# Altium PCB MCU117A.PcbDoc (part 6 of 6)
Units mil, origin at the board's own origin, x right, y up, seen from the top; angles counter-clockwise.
Board outline 2300 x 6749.64 mil, 6 copper layers (Top Signal, GND, Middle Signal, PWR, GND2, Bottom Signal), stack 61.64 mil thick; 424 components, 343 nets, 1563 pads, 921 vias.
Unrouted connection lines stored in the file: 4.
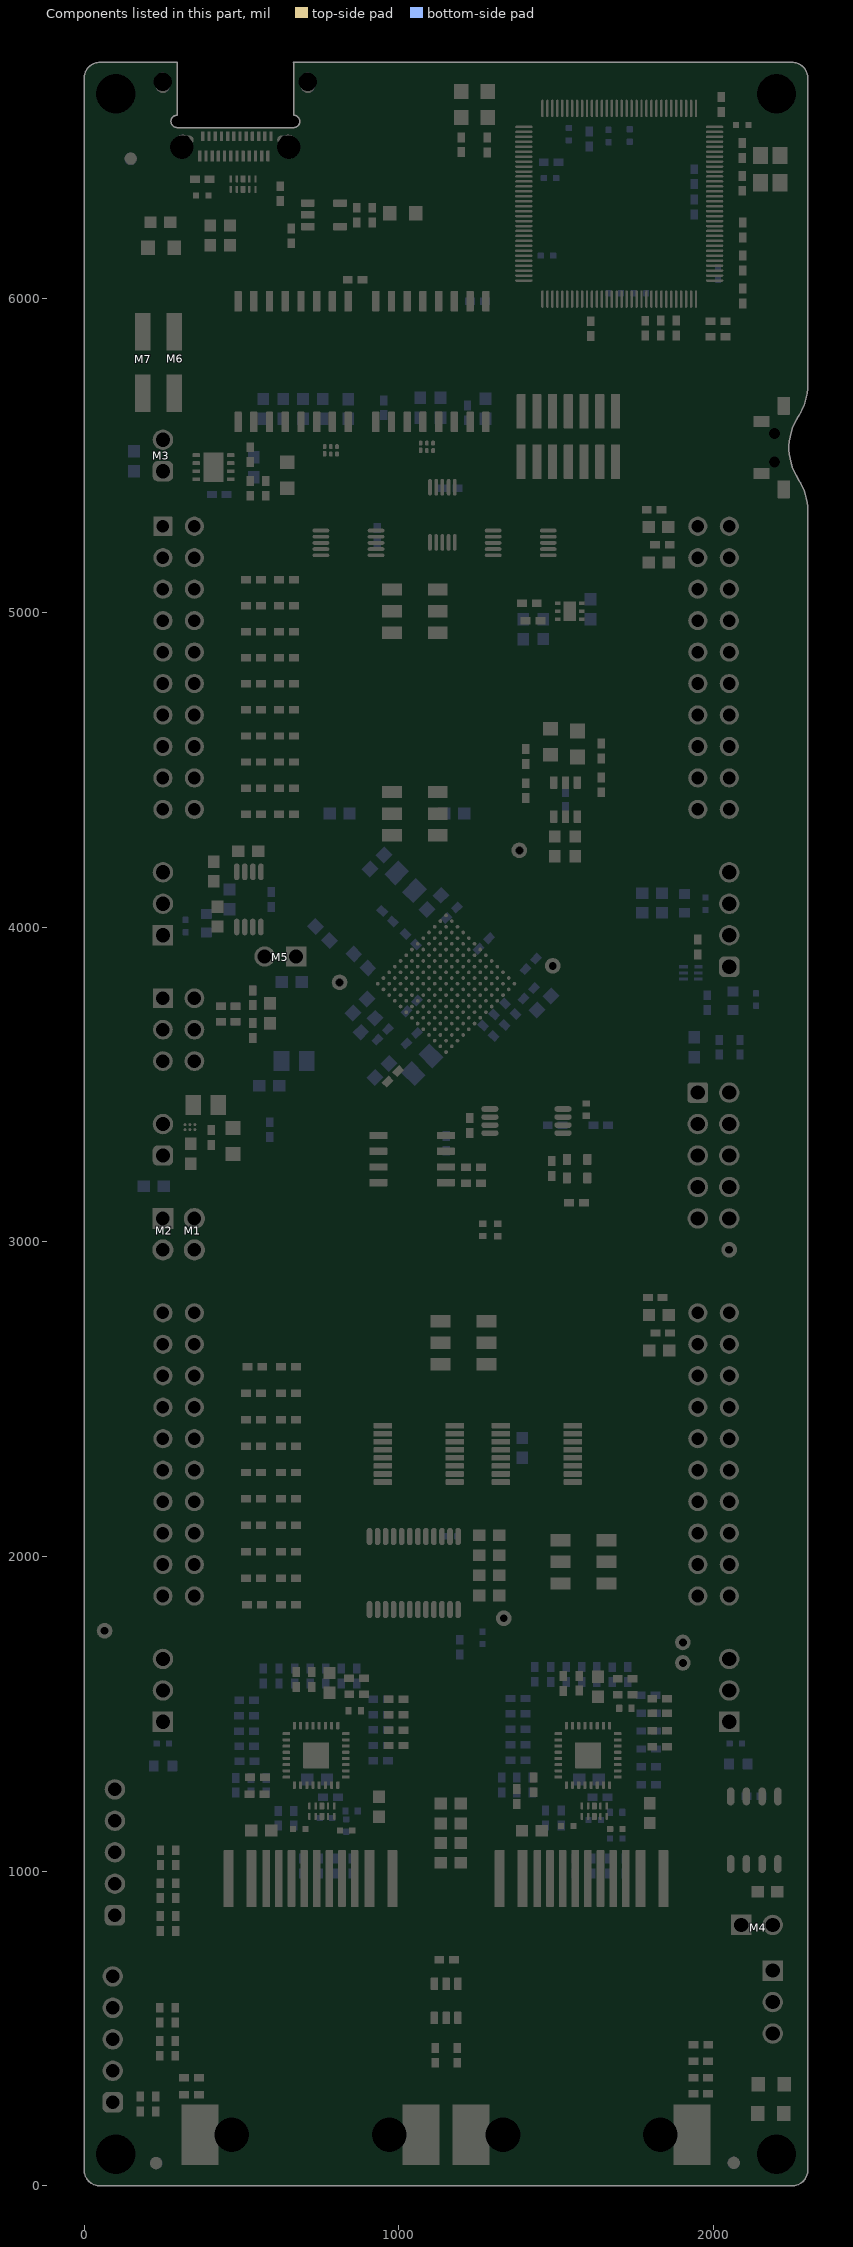
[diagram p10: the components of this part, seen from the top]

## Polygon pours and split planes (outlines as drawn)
VDDIO on PWR "PWR_VDDIO_P129" (solid, pour order 129): 1134.71,3836.63 1134.71,3752.07 1165.72,3752.07 1219.26,3805.61 1219.26,3833.54 1117,3935.81 1076.26,3895.07
VDD on PWR "PWR_VDD_P012" (solid, pour order 12): 1142.58,3884.02 1194.52,3884.02 1194.52,3737.01 1158.6,3737.01 1158.6,3866.88 1142.58,3866.88
VDD on PWR "PWR-VDD 1" (solid, remove dead copper, pour order 115): 1194.52,3847.16 1393,4045.64 1741.08,4045.64 1985.29,3801.43 2026.42,3760.31 2102.75,3760.31 2102.75,3760.55 2128.81,3786.61 2128.81,3935.74 2112.63,3951.92 2033.14,3951.92 1695.66,4289.41 1176.12,4289.41 968.18,4081.46 1151.71,3897.93 1130.2,3876.43 1157.99,3848.64 1157.99,3755.11 1150.89,3748.5 1173.13,3726.25 1194.52,3747.64
VDDA on PWR "PWR-VDDA" (solid, remove dead copper, pour order 63): 733.07,3520.72 868.8,3520.72 991.88,3643.8 967.11,3668.56 1111.46,3806.51 1120.65,3829.72 1120.65,3855.47 1031.91,3944.22 1012.42,3944.22 921.56,4035.08 969.67,4083.19 918.26,4134.6 633.87,4134.6 552.54,4053.28 550.83,3701.8
VDDIO on PWR "PWR_VDDIO_P089" (solid, remove dead copper, pour order 89): 951.95,3655.71 1163.76,3436.41 1739.06,4011.71 1626.38,4124.38 1471.19,4124.38 1196.14,3849.33 1196.14,3739.21 1153.49,3739.43 1153.49,3899.14 969.56,4083.08 921.56,4035.08 1113.49,3843.14 1113.49,3808.97
+3V3_XDS110 on PWR "PWR_+3V3_XDS110_P091" (solid, remove dead copper, pour order 91): 2139.88,6612 2245.98,6505.91 2245.98,6002.85 2245.98,5924.13 2161.85,5840 578.63,5840 519.87,5898.77 519.87,6062.37 821.92,6364.43 1195.43,6364.43 1443,6612
+5V0_USB on PWR "PWR_+5V0_USB_P096" (solid, remove dead copper, pour order 96): 42,5887.96 72.25,5850 487.44,5850 737.88,6277 1078.7,6277 1422.7,6621 2003,6621 2003.07,6621.07 2062.34,6621.07 2079.2,6637.94 2079.2,6708.26 2054.65,6732.81 1354.77,6732.81 1149.95,6527.99 545.98,6527.99 120.99,6527.99 42,6449
+1V2_MCU on PWR "PWR_+1V2_MCU_P097" (solid, remove dead copper, pour order 97): 1322.77,4948.77 1385,5011 1492.73,5011 1541.11,4962.61 1541.11,4652.24 1001.24,4112.37 959.44,4112.37 898.32,4173.5 898.32,4237.5 1322.77,4639.48
+5V0_MCU on PWR "PWR-No Net" (solid, remove dead copper, pour order 116): -0.01,212.95 12,194 358.63,194 378.34,218.93 374,1651.96 443.27,1721.23 1257.11,1721.89 1269,1733.78 1269,1812 1260.68,1828.24 208.08,1828.24 187.43,1848.89 187.61,1849.06 187.61,3130.55 288.45,3130.55 300,3119 300,3057.75 327.75,3030 422.38,3030 472.46,3074.64 472.46,3432.87 429.12,3476.2 213.97,3476.2 173,3501.37 173,3696 207.98,3727.09 446.96,3727.86 469.31,3750.21 469.31,3861.7 469.31,3848.53 469.31,4000.01 429.6,4039.72 217.07,4039.72 180,4076.78 180,5311 203.64,5334.64 284.85,5334.64 299.99,5319.5 299.99,5248.01 414.03,5248.01 433.38,5267.36 433.38,5320.04 211.23,5513.06 211.23,5747.95 16,5747.95 16,3953.78 25.48,3944.3 25.48,3879.84 -0.01,3879.84
VDD on PWR "PWR-VDD" (solid, remove dead copper, pour order 118): 1042.21,1828.27 1312.09,2098.15 1312.09,2280.94 1130.83,2462.2 984.57,2462.2 980.32,2457.95 757.49,2235.12 757.49,1958.27 887.49,1828.27
VDDIO on PWR "PWR-VDDIO" (solid, remove dead copper, pour order 120): 702.9,1732.26 1101.64,1732.26 1405.88,2036.5 1405.88,2346.41 1181.19,2571.1 790.44,2571.1 469.65,2250.31 469.65,1965.51
+3V3_MCU on PWR "PWR_+3V3_MCU_P126" (solid, remove dead copper, pour order 126): 13.52,5745.62 2286,5745.62 2294.66,5736.96 2284.74,5713.97 2284.74,5227.45 2284.74,0 22,0 13.52,8.48
GND on Top Signal "TOP_SIGNAL_GND_P124" (solid, remove dead copper, pour order 124): 21,5747.95 2303.05,5747.95 2305.03,5745.97 2269.64,5663.98 2269.64,0 21,0
GND on Top Signal "TOP_SIGNAL_GND_P125" (solid, remove dead copper, pour order 125): 1086.18,3776.48 1131.86,3838.79 1132.37,3838.79 1139.9,3846.32 1177.09,3846.32 1177.09,3814.14 1215.64,3814.14 1215.64,3780.47 1211.65,3776.48
+3V3_XDS110 on Top Signal "Top Signal-+3V3_XDS110" (solid, remove dead copper, pour order 100): 1368.17,6409.6 1368.17,6317 1368.63,6300.17 1483.03,6300.17 1500.98,6318.12 1500.98,6494.22 1429.03,6494.22 1421.32,6486.51 1421.32,6456.76 1368.17,6456.76
+5V0_USB on Top Signal "TOP_SIGNAL_+5V0_USB_P101" (solid, remove dead copper, pour order 101): 552.11,6322.52 559.99,6330.39 655.39,6330.39 655.39,6351.43 668.1,6364.14 745.81,6364.14 745.81,6287.9 742.63,6284.72 688.59,6284.72 680.98,6277.11 680.98,6252.89 687.87,6246 735.95,6246 745.81,6236.15 745.81,6209.53 731.86,6195.58 562.7,6195.58 547.13,6211.14
+5V0_USB on Top Signal "TOP_SIGNAL_+5V0_USB_P112" (solid, remove dead copper, pour order 112): 18.5,6039.01 211.24,6039.01 211.24,5840 18.5,5840
+3V3_MCU on Top Signal "TOP_SIGNAL_+3V3_MCU_P103" (solid, remove dead copper, pour order 103): 524.74,4210.7 532.01,4217.97 651.99,4217.97 666.67,4203.28 659.51,4196.12 659.51,4115.95 605.92,4062.36 524.74,4062.36
+3V3_MCU on Top Signal "TOP_SIGNAL_+3V3_MCU_P105" (solid, remove dead copper, pour order 105): 1920.44,4079.64 2012.53,4079.64 2039.36,4079.64 2128.81,3990.19 2128.81,3838.09 2107.03,3816.31 1917.92,3816.31
NetJ17_2 on Top Signal "TOP_SIGNAL_NETJ17_2_P107" (solid, remove dead copper, pour order 107): 255.19,3337.2 284.86,3366.87 329.08,3366.87 329.08,3401.67 323.33,3407.41 323.33,3463.54 368.66,3463.54 368.66,3404.02 369.06,3403.61 341.9,3402.76 341.9,3366.87 379.85,3366.87 408.95,3402.89 481.09,3402.89 481.09,3495.31 453.13,3523.26 261.03,3523.26 220,3482.23 220,3351.63 234.51,3337.12
+3V3_MCU on Top Signal "TOP_SIGNAL_+3V3_MCU_P109" (solid, remove dead copper, pour order 109): 447.44,5463.51 504.24,5463.51 505.82,5465.08 510.77,5460.13 510.77,5398.15 593.18,5398.15 623.88,5367.44 623.88,5281.5 603.93,5261.54 461.49,5261.54 445.93,5277.1
NetJ16_2 on Top Signal "TOP_SIGNAL_NETJ16_2_P110" (solid, remove dead copper, pour order 110): 218.79,5609.57 303.11,5609.57 382.94,5529.75 382.94,5389.12 351.78,5350.08 286.97,5406.2 286.97,5499.12 271.38,5514.72 218.79,5514.72
+5V0_MCU on Top Signal "TOP_SIGNAL_+5V0_MCU_P111" (solid, remove dead copper, pour order 111): 21,5747.95 219.7,5747.95 219.7,5569.12 293.39,5495.43 293.39,5400.64 295.61,5400.64 394.46,5301.8 394.46,5233.18 381.27,5220 16,5220
+5V0_MCU on Top Signal "Top Signal-+5V0_MCU" (solid, remove dead copper, pour order 113): 298.77,3036.19 310.94,3024.02 409.09,3024.02 428.73,3043.67 428.73,3198.04 428.73,3320.72 421.07,3328.38 356.89,3328.38 346.1,3339.17 346.1,3367.4 324.39,3389.11 283.05,3389.11 264.46,3370.52 264.46,3277.83 359.93,3277.83 370.25,3267.51 370.25,3140.35 354.67,3124.77 318.35,3124.77 298.77,3105.2
+3V3_ISO_JTAG on Top Signal "TOP_SIGNAL_+3V3_ISO_JTAG_P114" (solid, remove dead copper, pour order 114): 496.71,5724.2 518.13,5745.62 1713.35,5745.62 1755.31,5703.67 1755.31,5548.92 1713.61,5507.22 545.48,5507.22 496.16,5556.54
USB_GND on Top Signal "TOP_SIGNAL_USB_GND_P122" (solid, remove dead copper, pour order 122): 24.5,6732.81 2286,6732.81 2286,5840 24.5,5840
GND on Bottom Signal "BOTTOM_SIGNAL_GND_P106" (solid, remove dead copper, pour order 106): 21,5747.95 2292.22,5747.95 2301.76,5738.4 2292.22,5716.3 2292.22,16 21,16
USB_GND on Bottom Signal "BOTTOM_SIGNAL_USB_GND_P108" (solid, remove dead copper, pour order 108): 25.13,6749 2286,6749 2286,5873.4 2247,5850 50.39,5850 25.13,5869.52
GND on GND "GND_GND_P067" (solid, remove dead copper, pour order 67): -0.36,5747.95 2292.22,5747.95 2292.22,5229.77 2292.22,430.3 -0.36,430.3
ETH1_EARTH on GND "GND_ETH1_EARTH_P064" (solid, remove dead copper, pour order 64): 13.05,588.66 458.87,791.39 1857.19,791.39 2282,580.14 2282,0 13.05,0
USB_GND on GND "GND_USB_GND_P102" (solid, remove dead copper, pour order 102): -1821.32,7027.95 -1769.32,7079.95 392.68,7079.95 431.67,7040.95 431.67,6233.34 392.68,6209.95 -1803.93,6209.95 -1821.32,6223.38
USB_GND on GND "GND_USB_GND_P084" (solid, remove dead copper, pour order 84): -1789.32,7282.95 -1737.32,7334.95 424.68,7334.95 463.67,7295.95 463.67,6488.34 424.68,6464.95 -1771.93,6464.95 -1789.32,6478.38
USB_GND on GND "GND_USB_GND_P083" (solid, remove dead copper, pour order 83): 24.5,6732.81 2286,6732.81 2286,5840 24.5,5840
GND on GND2 "GND2_GND_P086" (solid, remove dead copper, pour order 86): 21,5747.95 2305.88,5747.95 2292.22,5716.29 2292.22,5229.77 2292.22,0 27,0 21,6
USB_GND on GND2 "GND2_USB_GND_P085" (solid, remove dead copper, pour order 85): 21,6720.36 49.64,6749 2286,6749 2286,5840 21,5840

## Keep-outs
Keep-Out Layer:
  lines w7.87: 295.27,6749.64 49.99,6749.64 ccw(c49.99,6699.64) -0.01,6699.64 -0.01,50 ccw(c49.99,50) 49.99,0 2249.99,0 ; 665.35,6749.64 2249.99,6749.64 cw(c2249.99,6699.64) 2299.99,6699.64 2299.99,5724.64 cw(c2118.33,5724.64) 2269.99,5624.64 ccw(c2421.66,5524.64) 2269.99,5424.64 cw(c2118.33,5324.64) 2299.99,5324.64 ; 2249.99,0.65 ccw(c2249.99,50.65) 2299.99,50.65 2293.99,5324.64
  text ".Layer_Name" at 464.64,-1242 h60

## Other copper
Top Signal:
  pour cut-out: 735.98,4527.62 737.35,4526.25 757.13,4526.25 757.13,4094.81 756.27,4093.94 735.98,4093.94
  pour cut-out: 1654.03,4256.72 1670.26,4272.95 1713.89,4272.95 1713.89,3981.57 1662.86,3981.57
  pour cut-out: 1105.42,3801.58 1113.76,3793.24 1113.76,3776.48 1086.18,3776.48
  pour cut-out: 1186.14,3794.95 1215.64,3794.82 1215.64,3780.47 1209.81,3774.64 1186.14,3774.64
  pour cut-out: 1214.06,3813.54 1215.64,3811.96 1215.64,3800.92 1215.14,3800.43 1211.39,3804.18 1211.39,3810.87
  text ".Layer_Name" at 473.64,-1239 h60
Middle Signal:
  text ".Layer_Name" at 476.64,-1238 h60
PWR:
  text ".Layer_Name" at 469.64,-1244 h60
GND:
  text ".Layer_Name" at 469,-1236 h60
GND2:
  text ".Layer_Name" at 470.64,-1242 h60
Bottom Signal:
  pour cut-out: 1395.87,4840 1818.28,4840 1818.28,4812.39 1395.87,4812.39
  pour cut-out: 1711,4303 1716.36,4308.36 1781.49,4308.36 1781.49,4297.54 1832.4,4246.64 1811.66,4225.9 1693.62,4225.9 1693.62,4292.21 1683.18,4302.64
  text ".Layer_Name" at 473.64,-1239 h60

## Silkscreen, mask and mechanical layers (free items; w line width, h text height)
Top Overlay:
  drawing of 12596 lines, arcs and shapes, not listed
  text "*" at 217.75,6362.53 h25
  text "*" at 244.53,6313.28 h25
  text "*" at 2217.9,6203.61 h25
  text "XRSn" at 2098,5694 h72.83
  text "GND" at 378.89,5625.4 h51.18 r90
  text "+5V0" at 113.49,5604.25 h45 r90
  text "ENABLE" at 15.74,5526.42 h51.18
  text "+3V3" at 66.49,5487.63 h51.18
  text "LDO" at 93.22,5447.32 h51.18
  text "IO.8" at 1773.67,5405.39 h51.18
  text "XDS110 Out" at 1404.42,5378.12 h51.18
  text "IO.9" at 1772.68,5367.67 h51.18
  text "*" at 1682.61,5313.88 h25
  text "*" at 1684.89,5201.76 h25
  text "IO.57" at 2114.49,5160.08 h51.18
  text "B0" at 144.72,5155 h51.18
  text "1" at 915.75,5105.59 h51.18
  text "1" at 1168.64,5103.57 h51.18
  text "A14" at 409.16,5094.2 h51.18
  text "IO.84" at 2114.49,5064.67 h51.18
  text "IO.43" at 87.44,5059.62 h51.18
  text "B14" at 409.16,5059.57 h51.18
  text "IO.6" at 1813.29,5059.64 h51.18
  text "*" at 682.3,5050.37 h25
  text "C14" at 409.16,5024.25 h51.18
  text "*" at 685.55,4966.78 h25
  text "SEL1" at 939.15,4961.32 h51.18 r90
  text "SEL2" at 1194.21,4961.32 h51.18 r90
  text "IO.7" at 1813.43,4959.64 h51.18
  text "IO.21" at 2114.49,4959.64 h51.18
  text "A4" at 408.02,4959.25 h51.18
  text "IO.42" at 86.87,4909.64 h51.18
  text "0" at 1166.94,4902.45 h51.18
  text "0" at 910.91,4897.73 h51.18
  text "*" at 684.96,4884.72 h25
  text "IO.10" at 1790.49,4859.64 h51.18
  text "XRSn" at 2114.49,4859.64 h51.18
  text "B4" at 408.02,4859.25 h51.18
  text "SEL1:" at 803.73,4837.28 h51.18
  text "IO42," at 981.04,4837.28 h51.18
  text "IO38," at 1161.42,4837.28 h51.18
  text "*" at 684.67,4802.07 h25
  text "SEL2" at 803.73,4787.28 h51.18
  text "IO43" at 981.04,4787.28 h51.18
  text "IO55" at 1161.42,4787.28 h51.18
  text "C0" at 142.45,4759.64 h51.18
  text "C4" at 408.02,4759.64 h51.18
  text "IO.11" at 1792.2,4759.64 h51.18
  text "IO.16" at 2114.49,4759.62 h51.18
  text ":" at 872.04,4726.78 h51.18
  text "0" at 837.04,4722.78 h51.18
  text "0" at 890.66,4722.78 h51.18
  text "XDS" at 1005.42,4722.78 h51.18
  text "BP" at 1198.71,4722.78 h51.18
  text "*" at 685.55,4718.26 h25
  text ":" at 872.91,4664.28 h51.18
  text "IO.18" at 86.59,4660.77 h51.18
  text "A7" at 408.02,4660.74 h51.18
  text "0" at 837.91,4660.28 h51.18
  text "1" at 897.91,4660.28 h51.18
  text "XDS" at 1005.42,4660.28 h51.18
  text "NC" at 1198.71,4660.28 h51.18
  text "IO.14" at 1789.88,4659.64 h51.18
  text "IO.17" at 2114.49,4659.64 h51.18
  text "*" at 685.26,4635.9 h25
  text ":" at 873.13,4602.28 h51.18
  text "1" at 843.13,4598.28 h51.18
  text "0" at 891.75,4598.28 h51.18
  text "BP" at 1027.42,4598.28 h51.18
  text "BP" at 1198.71,4598.28 h51.18
  text "IO.72" at 86.87,4559.64 h51.18
  text "B7" at 408.02,4559.64 h51.18
  text "IO.15" at 1790.97,4559.62 h51.18
  text "IO.12" at 2114.49,4559.64 h51.18
  text "*" at 684.38,4553.25 h25
  text ":" at 873.48,4540.86 h51.18
  text "1" at 843.48,4536.86 h51.18
  text "1" at 898.48,4536.86 h51.18
  text "BP" at 1027.42,4536.86 h51.18
  text "XDS" at 1182.17,4536.86 h51.18
  text "*" at 684.67,4470.61 h25
  text "IO.105" at 64.12,4459.64 h51.18
  text "C7" at 408.02,4459.64 h51.18
  text "IO.4" at 1813.01,4459.64 h51.18
  text "IO.23" at 2114.49,4459.64 h51.18
  text "1" at 917.13,4456.84 h51.18
  text "1" at 1170.02,4454.82 h51.18
  text "*" at 684.96,4387.67 h25
  text "IO.104" at 63.04,4359.64 h51.18
  text "A0" at 408.02,4359.64 h51.18
  text "IO.5" at 1814.09,4359.64 h51.18
  text "IO.133" at 2114.49,4359.64 h51.18
  text "*" at 685.55,4303.56 h25
  text "GPIO72" at 896.62,4286.89 h51.18 r90
  text "GPIO84" at 1230.83,4286.89 h51.18 r90
  text "0" at 1168.32,4253.7 h51.18
  text "0" at 912.28,4248.99 h51.18
  text "BOOT" at 984.62,4201.64 h51.18
  text "VDD" at 1272.12,4189.64 h51.18
  text "VREFHI" at 646.92,3987.64 h51.18
  text "VDDIO" at 1530.95,3845.45 h51.18
  text "*" at 620.46,3812.78 h25
  text "C8" at 408.82,3765.99 h51.18
  text "B8" at 119.03,3751.66 h51.18
  text "*" at 691.04,3708.33 h25
  text "VDDA" at 750.38,3699.87 h51.18
  text "B9" at 118.57,3648.11 h51.18
  text "*" at 633.37,3628.5 h25
  text "C9" at 408.57,3626.46 h51.18
  text "LAUNCHXL-F28P65X" at 1405.82,3610.57 h50 r0.23
  text "FSI" at 1932.39,3526.97 h51.18
  text "RXCLK" at 1700.22,3454.28 h51.18
  text "TXCLK" at 2109.99,3449.64 h51.18
  text "ENABLE" at 21.44,3350.75 h51.18
  text "+5V0" at 71.82,3312.62 h51.18
  text "BOOST" at 39.51,3272.31 h51.18
  text "TXD0" at 2109.99,3249.64 h51.18
  text "RXD0" at 1754.99,3239.64 h51.18
  text "RXD1" at 1774.99,3144.64 h51.18
  text "TXD1" at 2109.99,3144.64 h51.18
  text "*" at 1630.71,3109.97 h25
  text "+5V0 / TO / J7" at 419.99,2954.64 h51.18
  text "+3V3 / TO / J5" at 36.99,2948.66 h51.18
  text "GND" at 2078.85,2924.98 h51.18
  text "IO.2" at 1774,2903.44 h51.18
  text "IO.3" at 1774.15,2866.89 h51.18
  text "*" at 1681.27,2810.57 h25
  text "BP" at 1035.23,2734.03 h51.18
  text "BP" at 1325.23,2734.03 h51.18
  text "*" at 1680.84,2693.02 h25
  text "Q1" at 1031.33,2664.03 h51.18
  text "Q2" at 1325.23,2664.09 h51.18
  text "A5" at 142.99,2659.64 h51.18
  text "IO.94" at 2109.49,2659.64 h51.18
  text "A15" at 408.02,2594.53 h51.18
  text "J12" at 1010.23,2594.03 h51.18
  text "J13" at 1325.23,2594.03 h51.18
  text "IO.55" at 86.09,2559.64 h51.18
  text "B15" at 408.02,2559.93 h51.18
  text "IO.24" at 2109.49,2559.64 h51.18
  text "IO.0" at 1814.69,2554.64 h51.18
  text "*" at 694.41,2549.34 h25
  text "C15" at 408.02,2525.29 h51.18
  text "QEP Select" at 1083.93,2517.28 h51.18
  text "*" at 694.41,2464.58 h25
  text "IO.79" at 2109.49,2459.64 h51.18
  text "A8" at 409.02,2459.27 h51.18
  text "IO.1" at 1816.39,2449.64 h51.18
  text "IO.38" at 85.43,2409.67 h51.18
  text "*" at 694.6,2381.06 h25
  text "IO.99" at 1791.6,2359.64 h51.18
  text "XRSn" at 2109.49,2359.64 h51.18
  text "B3" at 408.02,2359.25 h51.18
  text "*" at 694.41,2297.73 h25
  text "C1" at 142.99,2259.64 h51.18
  text "C5" at 408.02,2259.69 h51.18
  text "IO.75" at 1792.03,2259.64 h51.18
  text "IO.91" at 2109.49,2259.64 h51.18
  text "*" at 694.6,2213.23 h25
  text "IO.32" at 1791.65,2164.64 h51.18
  text "IO.93" at 86.28,2159.62 h51.18
  text "A10" at 405.02,2159.62 h51.18
  text "IO.92" at 2109.49,2159.64 h51.18
  text "CAN" at 1542.32,2154.01 h51.18
  text "*" at 694.41,2129.04 h25
  text "ROUTE" at 1514.74,2110.02 h51.18
  text "BP" at 1426.36,2073.95 h51.18
  text "IO.82" at 85.71,2059.67 h51.18
  text "B6" at 408.02,2059.69 h51.18
  text "IO.13" at 2109.49,2059.64 h51.18
  text "IO.41" at 1793.26,2054.64 h51.18
  text "*" at 694.41,2044.21 h25
  text "*" at 1429.43,1988.74 h25
  text "IO.35" at 86.09,1959.62 h51.18
  text "C6" at 408.02,1959.67 h51.18
  text "*" at 694.41,1959.81 h25
  text "IO.37" at 1791.37,1959.64 h51.18
  text "IO.103" at 2109.49,1959.64 h51.18
  text "*" at 1430.97,1930.05 h25
  text "*" at 694.41,1877.03 h25
  text "IO.34" at 85,1859.64 h51.18
  text "B1" at 408.02,1859.6 h51.18
  text "IO.25" at 2109.49,1859.64 h51.18
  text "IO.36" at 1791.23,1854.64 h51.18
  text "XCVR" at 1375.55,1845.52 h51.18
  text "*" at 695.35,1793.36 h25
  text "+5V0" at 103.49,1749.07 h51.18
  text "CANTX" at 1742.33,1710.32 h51.18
  text "+3V3" at 1267.76,1686.31 h51.18
  text "CANRX" at 1738.92,1648.9 h51.18
  text "GND" at 10.97,1301.69 h51.18 r270
  text "*" at 1303.82,1199.92 h25
  text "5V" at 10.97,1186.69 h51.18 r270
  text "EQEP2" at 167.44,1124.54 h51.18 r270
  text "*" at 967.25,1101.14 h25
  text "*" at 1634.34,1095.42 h25
  text "2I" at 10.97,1083.07 h51.18 r270
  text "*" at 1792.01,1080.78 h25
  text "*" at 1307.23,1075.11 h25
  text "*" at 797.56,1072.85 h25
  text "2B" at 10.97,986.69 h51.18 r270
  text "2A" at 10.97,886.69 h51.18 r270
  text "P1" at 1051.77,861.56 h100
  text "P0" at 1916,861.56 h100
  text "GND" at 8.25,704.29 h51.18 r270
  text "HI" at 2282,667 h51.18 r90
  text "5V" at 8.25,589.29 h51.18 r270
  text "LO" at 2284.74,561.05 h51.18 r90
  text "CAN" at 2105.52,540.4 h60 r90
  text "EQEP1" at 165.22,530.81 h51.18 r270
  text "1I" at 8.25,480.04 h51.18 r270
  text "GND" at 2284.74,442.15 h51.18 r90
  text "1B" at 8.25,384.29 h51.18 r270
  text "1A" at 8.25,284.29 h51.18 r270
  text ".Layer_Name" at 467.64,-1242 h60
Bottom Overlay:
  drawing of 12861 lines, arcs and shapes, not listed
  text "LAUNCHXL-F28P65X / Development Kit" at 2299.99,6570.51 h100
  text "www.ti.com/launchpad" at 2299.99,5751.92 h100
  text "J3/J1" at 369.58,5346.31 h66.93
  text "J2/J4" at 2068.24,5343.78 h66.93
  text "40" at 1882.99,5259.64 h51.18
  text "39" at 1882.71,5163.74 h51.18
  text "2" at 182.99,5159.64 h51.18
  text "19" at 2161.99,5159.64 h51.18
  text "38" at 1882.99,5064.64 h51.18
  text "3" at 182.99,5059.64 h51.18
  text "23" at 466.99,5059.64 h51.18
  text "18" at 2161.99,5059.64 h51.18
  text "4" at 182.99,4959.64 h51.18
  text "24" at 466.99,4959.64 h51.18
  text "37" at 1882.99,4959.64 h51.18
  text "17" at 2161.99,4959.64 h51.18
  text "5" at 182.99,4859.64 h51.18
  text "25" at 466.99,4859.64 h51.18
  text "36" at 1882.99,4859.64 h51.18
  text "16" at 2161.99,4859.64 h51.18
  text "6" at 182.99,4759.64 h51.18
  text "26" at 466.99,4759.64 h51.18
  text "35" at 1882.99,4759.64 h51.18
  text "15" at 2161.99,4759.64 h51.18
  text "7" at 182.99,4659.64 h51.18
  text "27" at 466.99,4659.64 h51.18
  text "34" at 1882.99,4659.64 h51.18
  text "14" at 2161.99,4659.64 h51.18
  text "8" at 182.99,4559.64 h51.18
  text "28" at 466.99,4559.64 h51.18
  text "33" at 1882.99,4559.64 h51.18
  text "13" at 2161.99,4559.64 h51.18
  text "9" at 182.99,4459.64 h51.18
  text "29" at 466.99,4459.64 h51.18
  text "32" at 1882.99,4459.64 h51.18
  text "12" at 2161.99,4459.64 h51.18
  text "'.PRJ_Number'.PCB_Rev" at 1411.86,4458.85 h108.27
  text "10" at 182.99,4359.64 h51.18
  text "31" at 1882.99,4359.64 h51.18
  text "11" at 2151.99,4359.64 h51.18
  text "30" at 466.17,4358.97 h51.18
  text "*" at 1649.06,4096.47 h25
  text "*" at 478.48,3833.45 h25
  text "*" at 631.85,3626.61 h25
  text "*" at 478.52,3589.81 h25
  text "*" at 1348.02,3358.41 h25
  text "J6/J8" at 2072.3,2848.54 h66.93
  text "J7/J5" at 370.45,2847.62 h66.93
  text "80" at 1882.99,2764.64 h51.18
  text "42" at 182.99,2659.64 h51.18
  text "79" at 1882.99,2659.64 h51.18
  text "59" at 2166.99,2659.2 h51.18
  text "43" at 182.99,2559.64 h51.18
  text "63" at 466.99,2559.64 h51.18
  text "78" at 1882.99,2559.64 h51.18
  text "58" at 2166.99,2559.2 h51.18
  text "44" at 182.99,2459.64 h51.18
  text "64" at 466.99,2459.64 h51.18
  text "77" at 1882.99,2459.64 h51.18
  text "57" at 2166.99,2459.2 h51.18
  text "45" at 182.99,2359.64 h51.18
  text "65" at 466.99,2359.64 h51.18
  text "76" at 1882.99,2359.64 h51.18
  text "56" at 2166.99,2359.2 h51.18
  text "46" at 182.99,2259.64 h51.18
  text "66" at 466.99,2259.64 h51.18
  text "75" at 1882.99,2259.64 h51.18
  text "55" at 2166.99,2259.2 h51.18
  text "47" at 182.99,2159.64 h51.18
  text "67" at 466.99,2159.64 h51.18
  text "74" at 1882.99,2159.64 h51.18
  text "54" at 2166.99,2159.2 h51.18
  text "48" at 182.99,2059.64 h51.18
  text "68" at 466.99,2059.64 h51.18
  text "73" at 1882.99,2059.64 h51.18
  text "53" at 2166.99,2059.2 h51.18
  text "49" at 182.99,1959.64 h51.18
  text "69" at 466.99,1959.64 h51.18
  text "72" at 1882.99,1959.64 h51.18
  text "52" at 2166.99,1959.2 h51.18
  text "50" at 182.99,1859.64 h51.18
  text "70" at 466.99,1859.64 h51.18
  text "71" at 1882.99,1859.64 h51.18
  text "51" at 2156.99,1859.64 h51.18
  text "GND" at 223.26,1244.84 h51.18
  text "5V" at 52.99,1144.96 h51.18
  text "*" at 974.78,1127.22 h25
  text "*" at 696.41,1108.67 h25
  text "*" at 1554.5,1100.51 h25
  text "*" at 1804.16,1091.43 h25
  text "2I" at 47.36,1047.44 h51.18
  text "2B" at 52.4,949.92 h51.18
  text "2A" at 53.21,852.4 h51.18
  text "GND" at 215.1,653.12 h51.18
  text "5V" at 52.99,550.6 h51.18
  text "1I" at 46.16,452.35 h51.18
  text "1B" at 51.19,354.09 h51.18
  text "1A" at 52,255.84 h51.18
  text ".Layer_Name" at 464.64,-1239 h60
Top Paste:
  text ".Layer_Name" at 470.64,-1236 h60
Bottom Paste:
  text ".Layer_Name" at 461.64,-1239 h60
Top Solder:
  text ".Layer_Name" at 458.64,-1248 h60
Bottom Solder:
  text ".Layer_Name" at 455.64,-1233 h60
Drill Guide:
  text ".Layer_Name" at 479.64,-1237.5 h60
M1 Board Outline:
  lines w10: 294.91,6749 49.64,6749 ccw(c49.64,6699) -0.36,6699 -0.36,50 ccw(c49.64,50) 49.64,0 2249.64,0 ccw(c2249.64,50) 2299.64,50 2299.64,5324 ccw(c2117.97,5324) 2269.64,5424 cw(c2421.3,5524) 2269.64,5624 ccw(c2117.97,5724) 2299.64,5724 2299.64,6699 ccw(c2249.64,6699) 2249.64,6749 664.99,6749
  text ".Layer_Name" at 470.77,-1238.3 h60
M2 Board Dimensions:
  text ".Layer_Name" at 476.76,-1239.91 h60
M3 3D STEP Top:
  text ".Layer_Name" at 469.64,-1234.5 h60
M4 3D STEP Bottom:
  text ".Layer_Name" at 470.83,-1236.53 h60
M5 Assembly Top:
  lines w10: -395.86,-1306.67 6204.14,-1306.67 ; -395.86,-1103.34 6206.14,-1103.34 ; -395.86,-900 -395.86,-1510 3609.14,-1510 6206.14,-1510 6206.14,-900 -395.36,-900 -395.36,-1510 1180.14,-1510 ; 2069.14,-1510 2069.14,-900 ; 3336.14,-1103.34 3336.14,-900 ; 4176.14,-1103.34 4176.14,-900 ; 4798.14,-1516.5 4798.14,-1313.67
  text "COMPONENTS MARKED 'DNP' SHOULD NOT BE POPULATED." at 1049.64,-695 h60
  text "ASSEMBLY VARIANT:" at 1049.14,-810.5 h60
  text ".VariantName" at 2085.14,-810.5 h60
  text "PCB VIEWED FROM TOP SIDE" at -332.36,-1032.17 h60
  text "BOARD #:" at 2144.14,-1032.17 h60
  text ".PRJ_Number" at 2689.64,-1032.17 h60
  text "REV:" at 3534.14,-1032.17 h60
  text ".PCB_Rev" at 3825.64,-1032.17 h60
  text "SVN REV:" at 4372.14,-1032.17 h60
  text ".VersionControl_RevNumber" at 4878.14,-1032.17 h60
  text ".Layer_Name" at 476.14,-1236.5 h60
  text "TID #:" at 2144.14,-1235.5 h60
  text ".TID" at 2689.64,-1235.5 h60
  text "PLOT NAME =" at -332.36,-1440.84 h60
  text ".plot_File_Name" at 473.14,-1440.84 h60
  text "GENERATED    :" at 2146.14,-1440.84 h60
  text ".Print_Date" at 3015.64,-1440.84 h60
  text ".Print_Time" at 3744.64,-1440.84 h60
  text "TEXAS INSTRUMENTS" at 5009.14,-1440.84 h60
M6 Assembly Bottom:
  lines w10: -395.36,-1104.34 6206.64,-1104.34 ; -393.36,-1307.67 6206.64,-1307.67 ; 1012.64,-1517.5 1012.64,-1314.67 ; 1634.64,-1104.34 1634.64,-901 ; 2474.64,-1104.34 2474.64,-901 ; 3741.64,-1511 3741.64,-901 ; 4630.64,-1511 6206.14,-1511 6206.14,-901 -395.36,-901 -395.36,-1511 2201.64,-1511 6206.64,-1511 6206.64,-901
  text "COMPONENTS MARKED 'DNP' SHOULD NOT BE POPULATED." at 5999.14,-695 h60
  text ".VariantName" at 4955.14,-811 h60
  text "ASSEMBLY VARIANT:" at 5994.14,-811 h60
  text ".VersionControl_RevNumber" at 932.64,-1033.17 h60
  text "SVN REV:" at 1438.64,-1033.17 h60
  text ".PCB_Rev" at 1985.14,-1033.17 h60
  text "REV:" at 2276.64,-1033.17 h60
  text ".PRJ_Number" at 3121.14,-1033.17 h60
  text "BOARD #:" at 3666.64,-1033.17 h60
  text "PCB VIEWED FROM BOTTOM SIDE" at 6143.14,-1033.17 h60
  text ".Layer_Name" at 477.14,-1237 h60
  text ".TID" at 3121.14,-1236.5 h60
  text "TID #:" at 3666.64,-1236.5 h60
  text "TEXAS INSTRUMENTS" at 801.64,-1441.84 h60
  text ".Print_Time" at 2066.14,-1441.84 h60
  text ".Print_Date" at 2795.14,-1441.84 h60
  text "GENERATED    :" at 3664.64,-1441.84 h60
  text ".plot_File_Name" at 5337.64,-1441.84 h60
  text "PLOT NAME =" at 6143.14,-1441.84 h60
M7 LPKF Text Top:
  text ".Layer_Name" at 477.13,-1232.8 h60
M8 LPKF Text Bottom:
  text ".Layer_Name" at 477.77,-1238.04 h60
M9 Title Sheet:
  drawing of 57 lines, arcs and shapes, not listed
  text "1" at 635.47,7656.5 h70
  text "2" at 3131.14,7656.5 h70
  text "3" at 5620.48,7656.5 h70
  text "4" at 8127.15,7656.5 h70
  text "5" at 10626.14,7656.5 h70
  text "6" at 13131.14,7656.5 h70
  text "A" at -520.86,6513.5 h70
  text "A" at 14279.14,6513.5 h70
  text "B" at -520.86,4133.5 h70
  text "B" at 14279.14,4133.5 h70
  text "C" at -520.86,1758.5 h70
  text "C" at 14279.14,1758.5 h70
  text "PROJECT TITLE:" at 11239.14,-102.5 h45
  text ".PRJ_Title" at 11289.14,-235.83 h70
  text "DESIGNED FOR:" at 11239.14,-403.5 h45
  text ".PRJ_Customer" at 11289.14,-543.5 h70
  text "D" at -520.86,-611.5 h70
  text "D" at 14279.14,-611.5 h70
  text "FILE NAME:" at 11239.14,-703.5 h45
  text ".PCB_File_Name_No_Path" at 11289.14,-823.5 h70
  text "Texas Instruments (TI) and/or its licensors do not warrant the accuracy or completeness of this specification" at 6269.64,-985.34 h45
  text "ENGINEER:" at 11239.14,-993.5 h45
  text "LAYOUT BY:" at 12744.14,-993.5 h45
  text "or any information contained therein. TI and/or its licensors do not warrant that this design will meet" at 6224.65,-1098.01 h45
  text ".PRJ_Engineer" at 11289.14,-1148.49 h70
  text ".PCB_Layout" at 12794.64,-1148.49 h70
  text "the specifications, will be suitable for your application or fit for any particular purpose, or will operate in" at 6224.65,-1210.67 h45
  text ".Layer_Name" at 472.64,-1238.5 h60
  text "ALTIUM DESIGNER VERSION:" at 12744.14,-1303.5 h45
  text "an implementation. TI and/or its licensors do not warrant that the design is production worthy. You should" at 6224.65,-1323.34 h45
  text "completely validate and test your design implementation to confirm the system functionality for your application." at 6269.64,-1436 h45
  text ".print_Scale" at 11289.14,-1436.83 h70
  text ".Application_BuildNumber" at 12794.64,-1436.83 h70
  text "1" at 635.47,-1643.5 h70
  text "2" at 3131.14,-1643.5 h70
  text "3" at 5620.48,-1643.5 h70
  text "4" at 8127.15,-1643.5 h70
  text "5" at 10626.14,-1643.5 h70
  text "6" at 13131.14,-1643.5 h70
M10 Fab Notes:
  drawing of 189 lines, arcs and shapes, not listed
  text "DESIGN INFORMATION" at 12279.65,5983.17 h60
  text "MIN. TRACK WIDTH:" at 11635.1,5851.05 h60
  text "5" at 12731.34,5851.05 h60
  text "MIL" at 12886.1,5851.05 h60
  text "0.15" at 12630.64,5735 h60
  text "MIN. CLEARANCE:" at 11635.1,5726.92 h60
  text "mm" at 12886.1,5726.92 h60
  text "MIN. VIA PAD SIZE:" at 11635.1,5602.79 h60
  text "0.45" at 12630.64,5602.79 h60
  text "mm" at 12886.1,5602.79 h60
  text "0.05mm (2MIL)" at 12330.1,5472.89 h60
  text "MINIMUM ANNULAR RING" at 11305.86,5464.67 h60
  text "EXTERNAL" at 13038.1,5464.67 h60
  text "PER" at 11505.86,5354.55 h60
  text "IPC-D-275 CLASS 2 LEVEL C" at 11725.86,5354.54 h60
  text "MIL, HOLES" at 13214.1,5254.07 h60
  text "+/-" at 12821.64,5245.48 h60
  text "+/-" at 13675.64,5245.48 h60
  text "REGISTRATION TOLERANCES:" at 11305.86,5244.42 h60
  text "METAL" at 12505.64,5244.42 h60
  text "5" at 13081.84,5244.42 h60
  text "3" at 13914.84,5244.42 h60
  text "MIL" at 14031.1,5244.42 h60
  text "HOLE SIZE TOLERANCE (UNLESS OTHERWISE SPECIFIED):" at 11305.86,5146.1 h60
  text "+/-" at 13675.64,5143.23 h60
  text "5" at 13914.84,5142.17 h60
  text "MIL" at 14031.1,5142.16 h60
  text "MATERIAL:" at 11231.1,5004.52 h60
  text "FR-4 High Tg" at 12217.54,4875.99 h60
  text "X" at 12073.1,4868 h60
  text "FR-408" at 11652.1,4863.49 h60
  text "OTHER" at 13140.1,4863.49 h60
  text "62 MIL (1.6mm) +/-10%" at 11972.2,4720.46 h60
  text "X" at 11852.1,4718 h60
  text "THICKNESS:" at 11305.86,4712.24 h60
  text "OTHER" at 13257.1,4712.24 h60
  text "TOLERANCE:" at 11305.86,4573.92 h60
  text "ANSI IPC-6012 TYPE 3 CLASS 2" at 12332.11,4573.92 h60
  text "IPC-A600" at 13017.64,4447 h72.83
  text "OTHER +/-" at 12332.1,4429.73 h60
  text "X" at 12162.64,4427 h60
  text "BOW & TWIST:" at 11305.86,4284.54 h60
  text "ANSI IPC-6012 TYPE 3 CLASS 2" at 12332.11,4284.54 h60
  text "X" at 12152.64,4162 h60
  text "IPC-A600" at 13017.64,4142 h72.83
  text "OTHER +/-" at 12332.1,4137.85 h60
  text "DRILLING:" at 11231.1,4007.23 h60
  text "NC_DRILL FILES" at 12992.1,3902.04 h60
  text "REFERENCE:" at 11305.86,3898.1 h60
  text "X" at 11963.1,3898 h60
  text "AS SHOWN" at 12141.1,3898.1 h60
  text "X" at 12864.1,3898.1 h60
  text "OTHER" at 13290.1,3755.85 h60
  text "PTH COPPER THICKNESS:" at 11305.54,3752.32 h60
  text "X" at 12444.78,3752.32 h60
  text "20-30 um" at 12572.77,3752.32 h60
  text "BOARD FINISH:" at 11231.1,3604.72 h60
  text "SILKSCREEN:" at 11386.32,3494.6 h60
  text "X" at 12344.1,3494.6 h60
  text "TOP" at 12461.1,3494.6 h60
  text "X" at 12854.1,3494.6 h60
  text "BOTTOM" at 12972.1,3494.6 h60
  text "SILKSCREEN COLOR:" at 11386.32,3339.41 h60
  text "X" at 12343.1,3339.41 h60
  text "WHITE" at 12461.1,3339.41 h60
  text "OTHER" at 12972.1,3339.41 h60
  text "RED" at 13609.64,3206 h80
  text "GREEN" at 12592.1,3195.96 h60
  text "OTHER" at 13210.1,3195.96 h60
  text "X" at 13063.64,3192 h60
  text "SOLDER RESIST COLOR:" at 11386.32,3189.09 h60
  text "MATTE" at 12592.1,3041.71 h60
  text "SEMI-GLOSS" at 13209.64,3041.07 h60
  text "IMMERSION GOLD (ENIG)" at 12292.09,2868.94 h60
  text "ENEPIG" at 13629.64,2861.72 h60
  text "SURFACE FINISH:" at 11231.1,2860.72 h60
  text "IMM. TIN/SILVER OR EQUIV" at 11560.64,2723.4 h60
  text "X" at 11412.64,2722 h60
  text "OTHER" at 12992.1,2719.46 h60
  text "ARRAY/PANEL:" at 11231.1,2564.09 h60
  text "CUT AND TRIM PER M1 BOARD OUTLINE" at 12292.1,2555.86 h60
  text "X" at 12113.64,2554 h60
  text "N.C. ROUTE" at 12292.1,2419.9 h60
  text "V. SCORE" at 13158.1,2419.9 h60
  text "CERTIFICATION:" at 11231.1,2290.77 h60
  text "MATERIALS AND WORKMANSHIP FOR ALL PCBS" at 11956.1,2290.77 h60
  text "TO MEET OR EXCEED THE REQUIREMENTS OF:" at 11956.1,2196.71 h60
  text "X" at 13370.6,2070.39 h60
  text "X" at 11593.6,2068.08 h60
  text "ANSI IPC-A-600F CLASS ->" at 11721.6,2068.08 h60
  text "2" at 13479.6,2068.08 h60
  text "1" at 13164.6,2066.58 h60
  text "3" at 13833.6,2066.58 h60
  text "X" at 12405.6,1920.39 h60
  text "RoHS" at 12533.6,1920.39 h60
  text "OTHER" at 13178,1920.39 h60
  text "PER ORDER" at 13575.06,1920.39 h60
  text "ALL BOARDS MUST MEET OR EXCEED UL94-V0 REQUIREMENTS." at 11258.64,1766.57 h60
  text "PCB MUST BEAR THE UL94V-0 UL REGISTERED MATERIAL ID NUMBER" at 11258.64,1650.5 h60
  text "ADDITIONAL REQUIREMENTS:" at 11231.1,1481.08 h60
  text "MICROSECTION:" at 11305.86,1373.95 h60
  text "YES" at 12211.6,1373.95 h60
  text "X" at 12489.64,1232 h60
  text "REQUIRED" at 13073.1,1229.62 h60
  text "BARE BOARD ELEC. TEST:" at 11305.86,1226.76 h60
  text "NONE" at 12611.6,1226.76 h60
  text "PER ORDER" at 13665.1,1226.76 h60
  text "X" at 11367.6,1081.08 h60
  text "1) TOP & BOTTOM LAYER 5.906 MIL WIDE, 6 MIL SPACING, / TRACES REQUIRE 100 OHM DIFFERENTIAL IMPEDANCE" at 11457.26,1022.09 h50
  text "X" at 11364.6,916.08 h60
  text "2) TOP & BOTTOM LAYER 10.63 MIL WIDE, 5 MIL SPACING, / TRACES REQUIRE 90 OHM DIFFERENTIAL IMPEDANCE" at 11461.76,846.09 h50
  text "X" at 11362.6,748.08 h60
  text "3) TOP & BOTTOM LAYER 6 MIL WIDE, 6 MIL SPACING, / TRACES REQUIRE 50 OHM DIFFERENTIAL IMPEDANCE" at 11479.26,666.85 h50
  text "X" at 11363.6,587.08 h60
  text "4) TOP & BOTTOM LAYER 5 MIL WIDE, / TRACES REQUIRE 50 OHM SINGLE-ENDED IMPEDANCE" at 11481.26,492.85 h50
  text ".Layer_Name" at 483.52,-1237.37 h60
M12 Stackup:
  drawing of 399 lines, arcs and shapes, not listed
  text "Layer" at 5828.34,5874 h60
  text "Name" at 6238.26,5874 h60
  text "Material" at 7168,5874 h60
  text "Thickness" at 8027.77,5874 h60
  text "Constant" at 8677.6,5874 h60
  text "Board Layer Stack" at 9247.46,5874 h60
  text "Top Overlay" at 6238.26,5754 h60
  text "Top Solder" at 6238.26,5634 h60
  text "Solder Resist" at 7168,5634 h60
  text "0.40mil" at 8027.77,5634 h60
  text "3.5" at 8677.6,5634 h60
  text "1" at 5828.34,5514 h60
  text "Top Signal" at 6238.26,5514 h60
  text "CF-004" at 7168,5514 h60
  text "1.40mil" at 8027.77,5514 h60
  text "Dielectric 1" at 6238.26,5394 h60
  text "FR-4" at 7168,5394 h60
  text "6.25mil" at 8027.77,5394 h60
  text "4.2" at 8677.6,5394 h60
  text "2" at 5828.34,5274 h60
  text "GND" at 6238.26,5274 h60
  text "1.40mil" at 8027.77,5274 h60
  text "Dielectric 2" at 6238.26,5154 h60
  text "FR-4" at 7168,5154 h60
  text "16.10mil" at 8027.77,5154 h60
  text "4.2" at 8677.6,5154 h60
  text "3" at 5828.34,5034 h60
  text "Middle Signal" at 6238.26,5034 h60
  text "1.40mil" at 8027.77,5034 h60
  text "Dielectric 3" at 6238.26,4914 h60
  text "FR-4" at 7168,4914 h60
  text "8.54mil" at 8027.77,4914 h60
  text "4.2" at 8677.6,4914 h60
  text "4" at 5828.34,4794 h60
  text "PWR" at 6238.26,4794 h60
  text "1.40mil" at 8027.77,4794 h60
  text "Dielectric 4" at 6238.26,4674 h60
  text "FR-4" at 7168,4674 h60
  text "16.10mil" at 8027.77,4674 h60
  text "4.2" at 8677.6,4674 h60
  text "5" at 5828.34,4554 h60
  text "GND2" at 6238.26,4554 h60
  text "1.40mil" at 8027.77,4554 h60
  text "Dielectric 5" at 6238.26,4434 h60
  text "FR-4" at 7168,4434 h60
  text "6.25mil" at 8027.77,4434 h60
  text "4.2" at 8677.6,4434 h60
  text "6" at 5828.34,4314 h60
  text "Bottom Signal" at 6238.26,4314 h60
  text "CF-004" at 7168,4314 h60
  text "1.40mil" at 8027.77,4314 h60
  text "Bottom Solder" at 6238.26,4194 h60
  text "Solder Resist" at 7168,4194 h60
  text "0.40mil" at 8027.77,4194 h60
  text "3.5" at 8677.6,4194 h60
  text "Bottom Overlay" at 6238.26,4074 h60
  text ".Layer_Name" at 469.64,-1240.5 h60
M13 Component Bodies Top:
  text ".Layer_Name" at 478.59,-1235.73 h60
M14 Component Bodies Bottom:
  text ".Layer_Name" at 471.04,-1229.76 h60
M15 Courtyards Top:
  text ".Layer_Name" at 479.82,-1230.73 h60
M16 Courtyards Bottom:
  text ".Layer_Name" at 476.2,-1231.98 h60
Drill Drawing:
  drawing of 163 lines, arcs and shapes, not listed
  text "Symbol" at 5897.2,3710.47 h93.71
  text "Count" at 6288.54,3710.47 h93.71
  text "Hole Size" at 6717.5,3710.47 h93.71
  text "Plated" at 7485.97,3710.47 h93.71
  text "Hole Type" at 7823.39,3710.47 h93.71
  text "Drill Layer Pair" at 8311.84,3710.47 h93.71
  text "Hole Tolerance" at 9296.28,3710.47 h93.71
  text "18" at 6288.54,3548.52 h78.09
  text "7.87mil (0.200mm)" at 6717.5,3548.52 h78.09
  text "PTH" at 7485.97,3548.52 h78.09
  text "Round" at 7823.39,3548.52 h78.09
  text "Top Signal - Bottom Signal" at 8311.84,3548.52 h78.09
  text "903" at 6288.54,3386.57 h78.09
  text "8.00mil (0.203mm)" at 6717.5,3386.57 h78.09
  text "PTH" at 7485.97,3386.57 h78.09
  text "Round" at 7823.39,3386.57 h78.09
  text "Top Signal - Bottom Signal" at 8311.84,3386.57 h78.09
  text "A" at 5866.34,3376.58 h71.98
  text "8" at 6288.54,3224.62 h78.09
  text "25.00mil (0.635mm)" at 6717.5,3224.62 h78.09
  text "PTH" at 7485.97,3224.62 h78.09
  text "Round" at 7823.39,3224.62 h78.09
  text "Top Signal - Bottom Signal" at 8311.84,3224.62 h78.09
  text "2" at 6288.54,3062.66 h78.09
  text "27.56mil (0.700mm)" at 6717.5,3062.66 h78.09
  text "PTH" at 7485.97,3062.66 h78.09
  text "Slot" at 7823.39,3062.66 h78.09
  text "Top Signal - Bottom Signal" at 8311.84,3062.66 h78.09
  text "2" at 6288.54,2900.71 h78.09
  text "35.43mil (0.900mm)" at 6717.5,2900.71 h78.09
  text "NPTH" at 7485.97,2900.71 h78.09
  text "Round" at 7823.39,2900.71 h78.09
  text "Top Signal - Bottom Signal" at 8311.84,2900.71 h78.09
  text "80" at 6288.54,2738.76 h78.09
  text "40.16mil (1.020mm)" at 6717.5,2738.76 h78.09
  text "PTH" at 7485.97,2738.76 h78.09
  text "Round" at 7823.39,2738.76 h78.09
  text "Top Signal - Bottom Signal" at 8311.84,2738.76 h78.09
  text "10" at 6288.54,2576.81 h78.09
  text "43.31mil (1.100mm)" at 6717.5,2576.81 h78.09
  text "PTH" at 7485.97,2576.81 h78.09
  text "Round" at 7823.39,2576.81 h78.09
  text "Top Signal - Bottom Signal" at 8311.84,2576.81 h78.09
  text "10" at 6288.54,2414.86 h78.09
  text "43.31mil (1.100mm)" at 6717.5,2414.86 h78.09
  text "PTH" at 7485.97,2414.86 h78.09
  text "Round" at 7823.39,2414.86 h78.09
  text "Top Signal - Bottom Signal" at 8311.84,2414.86 h78.09
  text "+/-1.97mil" at 9296.28,2414.86 h78.09
  text "34" at 6288.54,2252.9 h78.09
  text "45.28mil (1.150mm)" at 6717.5,2252.9 h78.09
  text "PTH" at 7485.97,2252.9 h78.09
  text "Round" at 7823.39,2252.9 h78.09
  text "Top Signal - Bottom Signal" at 8311.84,2252.9 h78.09
  text "2" at 6288.54,2090.95 h78.09
  text "59.06mil (1.500mm)" at 6717.5,2090.95 h78.09
  text "PTH" at 7485.97,2090.95 h78.09
  text "Slot" at 7823.39,2090.95 h78.09
  text "Top Signal - Bottom Signal" at 8311.84,2090.95 h78.09
  text "2" at 6288.54,1929 h78.09
  text "74.80mil (1.900mm)" at 6717.5,1929 h78.09
  text "PTH" at 7485.97,1929 h78.09
  text "Slot" at 7823.39,1929 h78.09
  text "Top Signal - Bottom Signal" at 8311.84,1929 h78.09
  text "4" at 6288.54,1767.05 h78.09
  text "110.24mil (2.800mm)" at 6717.5,1767.05 h78.09
  text "NPTH" at 7485.97,1767.05 h78.09
  text "Round" at 7823.39,1767.05 h78.09
  text "Top Signal - Bottom Signal" at 8311.84,1767.05 h78.09
  text "+1.97mil/-1.18mil" at 9296.28,1767.05 h78.09
  text "4" at 6288.54,1605.09 h78.09
  text "125.00mil (3.175mm)" at 6717.5,1605.09 h78.09
  text "NPTH" at 7485.97,1605.09 h78.09
  text "Round" at 7823.39,1605.09 h78.09
  text "Top Signal - Bottom Signal" at 8311.84,1605.09 h78.09
  text "1079 Total" at 6288.54,1443.14 h78.09
  text "Slot definitions :" at 5897.2,1329.78 h78.09
  text "Routed Path Length" at 6484.35,1329.78 h78.09
  text "= Calculated from tool start centre position to tool end centre position." at 7187.46,1329.78 h78.09
  text "Hole Length" at 6484.35,1265 h78.09
  text "= Routed Path Length + Tool Size = Slot length as defined in the PCB layout" at 6927.18,1265 h78.09
  text ".Layer_Name" at 488.84,-1232.8 h60
Mechanical 17:
  text ".Layer_Name" at 481.66,-1236.76 h60
Mechanical 18:
  text ".Layer_Name" at 483.64,-1239.5 h60
Mechanical 19:
  text ".Layer_Name" at 483.8,-1231.98 h60

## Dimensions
-0.36,0 to 0.64,6750 on M2 Board Dimensions
-0.36,0 to 2299.64,0 on M2 Board Dimensions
